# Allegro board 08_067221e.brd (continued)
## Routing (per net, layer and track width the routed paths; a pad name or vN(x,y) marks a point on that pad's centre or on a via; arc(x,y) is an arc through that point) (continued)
UNNAMED_8_ADAU145X_I261_CLKOUT: length 3.2
  TOP w0.178: R88.1 36.71,37.08 35.69,38.1 35.69,38.48 35.38,38.78 U6.23
UNNAMED_8_ADAU145X_I261_DVDD1: length 21.1
  TOP w0.254: C78.2 36.53,35.31 36.05,35.31 35.65,35.7 35.65,36.98 35.37,37.27 35.32,37.27 35.31,37.28 U6.20 ; U6.53 26.21,46.46 25.4,47.27 ; U6.71 24.41,37.28 24.13,37 24.13,36.23 C76.2 ; C73.2 36.45,45.47 36.03,45.05 35.82,45.05 35.55,44.78 U6.35
  TOP w0.508: v1(21.59,35.94) 21.59,35.68 C52.2 23.16,35.43 C76.2 ; C73.2 36.87,45.8 36.87,46.52 C36.2 v1(37.22,47.49) ; v1(38.23,35.31) C42.2 37.17,34.66 C78.2 ; 25.4,47.27 24.92,47.75 C69.2 23.61,47.92 C23.1 23.61,49.92 v1(23.37,50.16)
  vias: v1(22.35,50.16) v1(22.86,50.16)
UNNAMED_8_ADAU145X_I261_LRCLKIN2: length 1.9
  TOP w0.178: U6.66 23.58,39.78 R81.2
UNNAMED_8_ADAU145X_I261_LRCLKIN3: length 1.9
  TOP w0.203: v1(25.91,38.28) U6.69
  BOTTOM w0.178: R183.2 v1(25.91,38.28)
UNNAMED_8_ADAU145X_I261_LRCLKOUT0: length 5.4
  TOP w0.178: R44.1 36.22,48.55 35.62,48.55 35.2,48.13 34.84,48.13 34.08,47.37 33.75,47.37 33.21,46.83 U6.39
UNNAMED_8_ADAU145X_I261_LRCLKOUT1: length 16
  TOP w0.178: U6.42 31.71,47.22 33,48.51 33.6,48.51 33.81,48.72 33.81,51.92 v1(33.53,52.2) ; R75.1 v1(38.98,49.16)
  BOTTOM w0.178: v1(38.98,49.16) 37.85,50.29 37.85,51.69 37.34,52.2 v1(33.53,52.2)
UNNAMED_8_ADAU145X_I261_LRCLKOUT2: length 7.6
  TOP w0.178: R49.1 29.75,52.7 29.87,52.58 29.87,48.72 29.21,48.05 U6.47
UNNAMED_8_ADAU145X_I261_LRCLKOUT3: length 3.5
  TOP w0.178: R50.1 26.92,48.77 27.71,47.99 U6.50
UNNAMED_8_ADAU145X_I261_MISO: length 2
  TOP w0.178: R76.1 36.19,42.28 U6.30
UNNAMED_8_ADAU145X_I261_MP7: length 3.5
  TOP w0.178: U6.46 29.71,47.87 30.61,48.77 R69.2
UNNAMED_8_ADAU145X_I261_PLLFILT: length 4.3
  TOP w0.203: U6.16 33.21,35.53 33.61,35.13 33.61,34.2 C58.1
  TOP w0.508: C58.1 R99.1
UNNAMED_8_ADAU145X_I261_SCLK: length 2.3
  TOP w0.178: U6.31 35.54,42.78 36.7,43.94 R64.2
UNNAMED_8_ADAU145X_I261_SCLM: length 2.1
  TOP w0.178: U6.28 35.94,41.28 R79.1
UNNAMED_8_ADAU145X_I261_SDAM: length 1.9
  TOP w0.178: U6.29 36.58,41.78 R77.1
UNNAMED_8_ADAU145X_I261_SDATAIN0: length 1.9
  TOP w0.178: U6.59 23.46,43.28 R66.2
UNNAMED_8_ADAU145X_I261_SDATAIN1: length 1.8
  TOP w0.178: U6.62 24,41.78 23.88,41.91 R67.2
UNNAMED_8_ADAU145X_I261_SDATAIN2: length 1.9
  TOP w0.178: U6.67 23.53,39.28 R68.2
UNNAMED_8_ADAU145X_I261_SDATAIN3: length 2.2
  TOP w0.178: U6.70 24.32,37.78 24,37.46 24,37.46 R71.2
UNNAMED_8_ADAU145X_I261_SDATAOUT2: length 3.2
  TOP w0.178: U6.49 28.21,49.02 R84.1
UNNAMED_8_ADAU145X_I261_SDATAOUT3: length 4.6
  TOP w0.178: R52.1 24.64,48.73 24.98,48.39 25.91,48.39 26.71,47.59 U6.52
UNNAMED_8_ADAU145X_I261_SPDIFIN: length 4.7
  TOP w0.178: U6.4 27.21,35.59 26.54,34.92 26.54,33.66 26.29,33.4 25.92,33.4 R193.2
UNNAMED_8_ADAU145X_I261_SPDIFOUT: length 4.2
  TOP w0.178: U6.5 27.71,35.46 26.92,34.68 26.92,33.27 R116.1
UNNAMED_8_ADAU145X_I261_SSM: length 2.2
  TOP w0.178: R85.1 35.8,40.28 U6.26
UNNAMED_8_ADAU145X_I261_THDM: length 17.6
  TOP w0.178: U6.63 23.71,41.28 23.67,41.25 21.56,41.25 21.21,40.89 21.21,40.04 20.15,38.99 20.15,31.6 TP17.1
UNNAMED_8_ADAU145X_I261_THDP: length 18.8
  TOP w0.178: TP16.1 24.32,29.97 22.48,29.97 20.54,31.92 20.54,38.8 21.59,39.85 21.59,40.64 21.82,40.87 23.6,40.87 23.68,40.78 U6.64
UNNAMED_8_ADAU145X_I261_VDRIVE: length 11.5
  TOP w0.203: v1(26.71,38.09) U6.3
  BOTTOM w0.508: R175.1 22.86,44.69 Q3.1 23.5,42.92 26.71,39.72 v1(26.71,38.09)
UNNAMED_8_ADAU145X_I261_XTALIN: length 7.5
  TOP w0.178: U6.21 35.45,37.78 36.07,37.16 36.07,36.13 36.37,35.83 39,35.83 JP38.2
UNNAMED_8_CAP_I196_N2: length 1.4
  TOP w0.508: C86.2 35.56,31.41 R99.2
UNNAMED_8_CN3P_I266_N1: length 2.2
  TOP w0.203: JP38.1 R109.2
UNNAMED_8_CN3PV16_I292_VOUT: length 3.4
  TOP w0.203: P4.1 R103.1
UNNAMED_8_CN10P_I309_N1: length 4.4
  BOTTOM w0.203: P30.1 147.7,4.34 R234.2
UNNAMED_8_CN10P_I309_N3: length 4.4
  BOTTOM w0.203: R233.2 150.11,4.47 P30.3
UNNAMED_8_CN10P_I309_N4: length 5.9
  TOP w0.203: P30.4 153.19,7.57 153.19,10.89 R155.2
UNNAMED_8_CN10P_I309_N5: length 4.4
  BOTTOM w0.203: R232.2 152.65,4.47 P30.5
UNNAMED_8_CN10P_I309_N6: length 1.4
  BOTTOM w0.203: R225.2 P30.6
UNNAMED_8_CN10P_I309_N7: length 4.4
  BOTTOM w0.203: R235.2 155.19,4.47 P30.7
UNNAMED_8_CN10P_I309_N8: length 1.4
  BOTTOM w0.203: R223.2 P30.8
UNNAMED_8_CN10P_I309_N9: length 8.7
  TOP w0.203: JP42.2 P30.9
  BOTTOM w0.203: P30.9 159.03,3.25 R231.2
UNNAMED_8_DIOLED_I175_P: length 1.8
  TOP w0.178: DS4.A 38.1,51.46 R75.2
UNNAMED_8_DIOLED_I315_P: length 1.8
  TOP w0.203: R155.1 DS5.A
UNNAMED_8_RES_I3_N2: length 4
  TOP w0.203: R115.1 41.51,25.65 41.72,25.86 Y1.1 43.24,27.38 R110.2
UNNAMED_8_RES_I27_N1: length 1.9
  TOP w0.203: Y1.3 39.82,30.9 R109.1
UNNAMED_8_RES_I113_N2:
  vias: v1(22.35,52.45) v1(22.86,52.45) v1(23.37,52.45)
UNNAMED_9_AD1937_I165_ABCLK: length 8.6
  TOP w0.178: U7.28 53.57,43.98 v1(53.61,43.94) ; U7.21 57.08,46.44 56.9,46.62 56.9,46.66 R58.2
  TOP w0.203: U7.21 v1(57.08,43.99)
  BOTTOM w0.178: v1(53.61,43.94) 54.13,43.42 56.5,43.42 v1(57.08,43.99)
UNNAMED_9_AD1937_I165_ADC2LN: length 5
  TOP w0.254: R43.1 54.8,29.87 54.8,30.53 56.02,31.75 56.02,32.72 56.08,32.78 U7.58
UNNAMED_9_AD1937_I165_ADC2LP: length 5.2
  TOP w0.254: U7.57 55.56,33.99 55.56,31.94 53.82,30.2 53.82,29.98 R60.1
UNNAMED_9_AD1937_I165_ADC2RN: length 4.5
  TOP w0.254: U7.60 57.08,32.49 56.93,32.34 56.93,31.37 56.71,31.14 R61.1
UNNAMED_9_AD1937_I165_ADC2RP: length 4.7
  TOP w0.254: R124.1 55.63,30.71 56.48,31.56 56.48,32.53 56.57,32.63 U7.59
UNNAMED_9_AD1937_I165_ALRCLK: length 9.2
  TOP w0.178: U7.29 53.08,47 R59.2
  TOP w0.203: U7.22 56.57,44.25 56.54,44.22 56.54,43.77 56.57,43.74 56.57,43.62 56.1,43.14 53.38,43.14 53.08,43.45 U7.29
UNNAMED_9_AD1937_I165_ASDATA1: length 1.7
  TOP w0.203: U7.27 54.08,47.03 R105.1
UNNAMED_9_AD1937_I165_DSDATA1: length 1.7
  TOP w0.203: U7.20 R104.2
UNNAMED_9_AD1937_I165_FILTR: length 1.8
  TOP w0.254: U7.47 C127.2
UNNAMED_9_AD1937_I165_LF: length 2.1
  TOP w0.254: C60.2 57.57,31.9 U7.61
UNNAMED_9_AD1937_I165_SCL: length 5.7
  TOP w0.203: R132.1 49.52,46.3 50.8,45.02 50.8,43.19 50.53,42.93 U7.34
UNNAMED_9_AD1937_I165_SDA: length 13.5
  TOP w0.203: U7.31 52.08,43.87 53.21,42.74 58.48,42.74 60.83,45.09 R138.1
UNNAMED_10_ADG774_I1_D1: length 2.1
  TOP w0.178: U8.4 3.66,36.33 R92.2
UNNAMED_10_ADG774_I1_D2: length 2.4
  TOP w0.178: R111.2 3.46,31.62 4.36,32.52 U8.7
UNNAMED_10_ADG774_I1_D3: length 2
  TOP w0.178: R113.2 12.06,31.25 U8.9
UNNAMED_10_ADG774_I1_D4: length 1.9
  TOP w0.178: R100.2 12.44,35.06 U8.12
UNNAMED_10_ADG774_I1_ENN: length 3.1
  TOP w0.178: R83.1 R82.1 12.44,38.87 U8.15
UNNAMED_10_ADG774_I1_IN: length 15.7
  TOP w0.508: JP47.2 3.75,50.8 4.95,49.59 4.95,42.8 5.41,42.34 R80.1 U8.1
UNNAMED_10_ADG774_I1_S1A: length 2.4
  TOP w0.178: U8.2 4.43,38.87 R86.2
UNNAMED_10_ADG774_I1_S1B: length 2.3
  TOP w0.178: R90.1 4.04,37.6 U8.3
UNNAMED_10_ADG774_I1_S2A: length 2.1
  TOP w0.178: U8.5 3.56,35.06 R97.2
UNNAMED_10_ADG774_I1_S2B: length 2.2
  TOP w0.178: R102.1 3.94,33.79 U8.6
UNNAMED_10_ADG774_I1_S3A: length 1.9
  TOP w0.178: R106.2 12.44,33.79 U8.11
UNNAMED_10_ADG774_I1_S3B: length 2
  TOP w0.178: R108.1 12.19,32.52 U8.10
UNNAMED_10_ADG774_I1_S4A: length 2
  TOP w0.178: R89.2 12.06,37.6 U8.14
UNNAMED_10_ADG774_I1_VDD: length 9.5
  TOP w0.305: C38.2 11.05,41.66 11.68,41.02 13.21,41.02 13.45,40.77 R83.2
  TOP w0.508: 10.5,43.41 10.53,43.38 C38.2 10.53,40.21 U8.16 ; 10.5,43.41 E9.1 ; 10.5,43.41 C37.2
UNNAMED_10_ADMAX16823_I78_CS1: length 12.7
  TOP w0.203: R153.2 TP20.1 9.52,10.61 DS6.3 10.72,12.88 11.49,13.65 11.49,15.16 12.21,15.87 U10.15
UNNAMED_10_ADMAX16823_I78_CS2: length 11.5
  TOP w0.203: U10.14 11.56,15.8 11.05,15.29 11.05,14.22 10.76,13.94 DS6.2 TP22.1 R152.2
UNNAMED_10_ADMAX16823_I78_CS3: length 12.3
  TOP w0.203: U10.13 10.91,17.67 11.1,17.48 11.1,15.99 10.11,15 DS6.1 7.65,15 7.58,15.07 4.94,15.07 TP23.1 R151.2
UNNAMED_10_ADMAX16823_I78_LGC: length 1.6
  TOP w0.203: C15.2 8.96,18.22 U10.10
UNNAMED_10_ADMAX16823_I78_OUT1: length 16.4
  TOP w0.203: DS6.4 13.45,12.88 14.43,13.86 14.43,15.65 13.91,16.18 13.91,25.34 13.26,25.98 12.41,25.98 12.21,25.78 U10.2
UNNAMED_10_ADMAX16823_I78_OUT2: length 12.6
  TOP w0.203: DS6.5 13.45,13.94 14.03,14.52 14.03,15.48 13.46,16.05 13.46,24.84 13.26,25.04 U10.1
UNNAMED_10_ADMAX16823_I78_OUT3: length 4.4
  TOP w0.203: DS6.6 12.92,18.4 12.86,18.47 U10.16
UNNAMED_10_ADMAX16823_I78_REG: length 1.5
  TOP w0.203: U10.11 9.61,17.94 C87.2
UNNAMED_10_FERRITE_I73_N1: length 1.7
  TOP w0.508: C85.2 7.18,19.95 ; C85.2 7.76,19.41 ; C85.2 6.59,19.41
UNNAMED_10_RES_I13_N2: length 11.5
  TOP w0.178: R108.2 v1(14.23,32.26)
  TOP w0.203: U10.5 v1(10.26,27.94)
  BOTTOM w0.178: v1(10.26,27.94) 12.19,27.94 14.22,29.97 14.22,32.25 v1(14.23,32.26) R108.2
UNNAMED_10_RES_I16_N2: length 17.2
  TOP w0.178: R102.2 v1(2.42,32.52) 2.43,32.51 3.81,32.51 4.21,32.91 4.21,32.96 4.39,33.15 6.6,33.15 6.93,32.82 7.95,32.82 8.25,32.51 8.25,29.97 9.53,28.7 10.73,28.7 10.91,28.52 U10.4
  BOTTOM w0.178: R102.2 v1(2.42,32.52)
UNNAMED_10_RES_I19_N2: length 22.9
  TOP w0.178: R90.2 v1(2.42,37.4) 3.69,37.4 4.1,36.99 6.45,36.99 7.17,37.72 8.38,37.72 8.65,37.45 8.65,30.12 9.68,29.08 11.05,29.08 11.29,28.84 11.29,28.84 11.56,28.57 U10.3
  BOTTOM w0.178: R90.2 v1(2.42,37.4)
UNNAMED_11_CAP_I16_N2: length 10.7
  TOP w0.508: 122.41,15.56 E12.1 ; E12.1 123.16,16.43 ; E12.1 123.16,14.68 ; C75.2 v1(120.92,19.08) ; C89.2 v1(110.92,13.55) ; C96.2 v1(109.71,3.08) ; C77.2 v1(101.34,19.08)
  BOTTOM w0.203: v1(110.92,14.63) v1(110.92,13.55)
  BOTTOM w0.508: v1(120.92,20.4) v1(120.92,19.08) ; v1(100.92,20.4) 101.34,19.99 v1(101.34,19.08) ; v1(110.92,3.08) v1(109.71,3.08)
  vias: v1(112.6,3.9) v1(122.05,16.26) v1(122.05,15.62) v1(122.05,14.99) v1(122.6,21.22)
UNNAMED_11_CN2P_I108_N1: length 2.3
  TOP w0.203: JP3.1 R74.1
UNNAMED_11_CN2P_I108_N2: length 10
  TOP w0.203: R246.2 U21.7 137.92,9.4 137.67,9.14 137.67,5.46 136.27,4.06
UNNAMED_11_FERRITE_I94_N1: length 2
  TOP w0.508: E16.1 139.85,10.69 U21.8
UNNAMED_11_IC24XX512_I83_A0: length 3.3
  TOP w0.203: 134.75,10.67 v1(133.1,10.67) R15.1
  BOTTOM w0.203: R16.2 v1(133.1,10.67)
UNNAMED_11_IC24XX512_I83_A1: length 3.3
  TOP w0.203: 134.75,9.4 v1(133.1,9.4) R19.1
  BOTTOM w0.203: R24.2 v1(133.1,9.4)
UNNAMED_11_IC24XX512_I83_A2: length 3.3
  TOP w0.203: 134.75,8.13 v1(133.1,8.13) R26.1
  BOTTOM w0.203: R30.2 v1(133.1,8.13)
UNNAMED_11_IC24XX512_I83_SCL: length 2
  TOP w0.203: 139.83,8.13 R25.1
UNNAMED_11_IC24XX512_I83_SDA: length 2
  TOP w0.203: U21.5 R29.1
UNNAMED_11_ICT3902_I102_CLK: length 44.8
  TOP w0.203: R157.1 v1(109.79,15.45)
  BOTTOM w0.203: 111.63,12.95 111.63,14.74 110.92,15.45 ; 111.63,12.95 112.9,12.95 113.92,13.97 113.92,15.62 115.57,17.27 117.73,17.27 119.13,18.67 119.13,19.81 120.54,21.22 v1(120.92,21.22) ; 111.63,12.95 109.6,10.92 109.6,5.22 v1(110.92,3.9) ; v1(110.92,15.45) v1(109.79,15.45) 107.21,18.03 100.2,18.03 99.57,18.67 99.57,20.83 99.96,21.22 v1(100.92,21.22) ; v1(110.92,15.45) 110.92,15.45 ; v1(110.92,15.45) 110.92,15.45 ; v1(110.92,15.45) 110.92,15.45 ; 110.92,15.45 110.92,15.45
UNNAMED_11_ICT3902_I102_DATA: length 2.1
  TOP w0.203: R130.1 v1(122.6,19.11)
  BOTTOM w0.203: v1(122.6,19.11) v1(122.6,20.4)
UNNAMED_11_ICT3902_I103_DATA: length 2.4
  TOP w0.203: R131.1 v1(103.37,19.11)
  BOTTOM w0.203: v1(102.6,20.4) 103.37,19.63 v1(103.37,19.11)
UNNAMED_11_ICT3902_I104_DATA: length 2
  TOP w0.203: R158.1 v1(113.83,3.08)
  BOTTOM w0.203: v1(112.6,3.08) v1(113.83,3.08)
UNNAMED_11_ICT3902_I105_DATA: length 1.9
  TOP w0.203: R141.1 v1(112.6,13.59)
  BOTTOM w0.203: v1(112.6,14.63) v1(112.6,13.59)
UNNAMED_12_ADLT3502_I229_BD: length 14.8
  L3_SIG w0.305: v1(58.86,61.02) 59.4,60.49 59.4,58.59 60.33,57.66 63.37,57.66 64.77,56.26 v1(64.77,52.58)
  BOTTOM w0.203: U16.2 59.01,61.94 R160.1 v1(58.86,61.02)
UNNAMED_12_ADLT3502_I229_BOOST: length 1.3
  BOTTOM w0.203: U16.7 C113.1
UNNAMED_12_ADLT3502_I229_DA: length 4.3
  BOTTOM w0.203: U16.6 62.65,62.39 62.87,62.61 62.87,63.25 62.36,63.75 62.36,65.02 D1.A
UNNAMED_12_ADLT3502_I229_SHDNN: length 5.9
  BOTTOM w0.203: R162.1 55.53,62.79 C105.2 56.71,63.23 56.91,63.44 60,63.44 60.2,63.23 U16.4
UNNAMED_12_ADLT3502_I229_SW: length 4.5
  BOTTOM w0.203: 61.98,61.28 61.98,61.28 U16.8
  BOTTOM w0.508: C113.2 63.89,60.94 ; C113.2 62.72,60.94 ; C113.2 63.31,60.39 ; D1.C 65.5,65.53 ; D1.C 64.65,64.68 ; D1.C 64.65,66.38
UNNAMED_12_ADLTC4368V2_I398_SHDNN: length 2.3
  TOP w0.254: R27.1 54.47,56.98 U3.6
UNNAMED_12_ADP2360_I325_FB: length 4.6
  BOTTOM w0.203: U19.4 85.33,60.22 85.85,59.69 R164.2 R167.1 85.92,57.36 C115.2
UNNAMED_12_ADP2360_I325_ITH: length 1.8
  BOTTOM w0.203: R163.2 85.83,60.87 U19.3
UNNAMED_12_ADP2360_I325_SS: length 1.4
  BOTTOM w0.203: U19.5 C25.2
UNNAMED_12_CAP_I278_N2: length 19
  TOP w0.508: 28.51,59.31 TP1.1 ; TP1.1 30.29,57.53 ; TP1.1 30.29,59.31 ; TP1.1 28.51,57.53 ; 23.89,62.8 P1.1 ; P1.1 23.89,60.49 ; P1.1 26.2,62.8 ; P1.1 26.2,60.49 ; 32.63,62.78 P2.1 ; P2.1 35.25,62.78 ; P2.1 35.25,65.4 ; P2.1 32.63,65.4
UNNAMED_12_CAP_I279_N2: length 2.8
  TOP w0.254: U3.1 48.71,58.98 48.46,59.23 48.46,59.56 v1(48.45,59.56)
  TOP w0.508: R17.2 v1(45.02,60.07) ; R10.2 v1(43.43,61.32)
  vias: v1(39.69,59.82) v1(39.69,59.12) v1(40.45,59.82) v1(40.45,59.12) v1(41.21,59.82) v1(41.21,59.12) v1(46.48,64.33) v1(46.48,63.56) v1(46.48,62.86) v1(46.48,62.1) v1(49.21,59.56)
UNNAMED_12_CAP_I301_N2: length 13.2
  L3_SIG w0.305: v1(80.58,52.01) 85.72,57.15 v1(88.71,57.15)
  BOTTOM w0.305: v1(88.71,57.15) C115.1 87.76,57.18 87.76,58.1 87.31,58.55 R167.2
UNNAMED_12_CAP_I303_N2: length 3.6
  TOP w0.254: U3.4 47.44,57.48 46.94,56.97 R28.1 C6.2
UNNAMED_12_CAP_I350_N2: length 1.1
  TOP w0.203: R13.1 C3.2
UNNAMED_12_DIOLED_I290_P: length 1.6
  TOP w0.508: DS8.A R33.1
UNNAMED_12_DIOLED_I334_P: length 1.9
  TOP w0.508: DS2.A R10.1
UNNAMED_12_DIOLED_I356_P: length 1.6
  TOP w0.508: R36.1 DS7.A
UNNAMED_12_RES_I210_N1: length 3.4
  TOP w0.254: U3.3 46.81,57.98 R20.1 R23.2
UNNAMED_12_RES_I210_N2: length 3.6
  TOP w0.254: U3.2 47.46,58.48 46.95,58.98 R20.2 R17.1
UNNAMED_12_TRANNMOSFETDUAL_I282_S:
  vias: v1(54.93,65.53) v1(54.93,64.14) v1(55.69,65.53) v1(55.69,64.14)
UNNAMED_13_ADA48412_I26_: length 4.2
  BOTTOM w0.203: R205.2 C157.1 R204.1 22.17,14.78 U18.6
UNNAMED_13_ADA48412_I26_OUT: length 12.6
  BOTTOM w0.203: R214.2 26.09,15.72 25.76,16.05 ; 25.76,16.05 U18.7 22.17,16.05 R204.2 C157.2 ; 25.76,16.05 26.25,16.53 R200.1
UNNAMED_13_ADA48412_I42_: length 7.9
  BOTTOM w0.203: R214.1 27.09,15.28 27.86,16.05 U18.2 31.02,16.05 R201.1
UNNAMED_13_ADA48412_I42_OUT: length 5.5
  BOTTOM w0.203: R198.1 27.6,17.46 27.74,17.32 U18.1 31.06,17.32 R201.2
UNNAMED_13_ADA48412_I53_: length 6.7
  BOTTOM w0.203: R213.1 38.47,14.11 37.8,14.78 U17.6 34.68,14.78 R202.1
UNNAMED_13_ADA48412_I53_OUT: length 6.9
  BOTTOM w0.203: R202.2 34.42,16.05 U17.7 37.89,16.05 38.44,16.6 R197.1
UNNAMED_13_ADA48412_I115_: length 3.3
  BOTTOM w0.203: R221.2 C161.2 57.66,22.67 57.15,23.18 U5.3
UNNAMED_13_ADA48412_I115__1: length 5.2
  BOTTOM w0.203: R219.2 C155.1 57.29,24.72 57.02,24.45 U5.2
UNNAMED_13_ADA48412_I115_OUT: length 9.3
  TOP w0.203: v1(54.29,25.78) 53.09,25.78 51.05,23.74 R236.1
  BOTTOM w0.203: R217.2 C155.2 U5.1 56.2,25.78 v1(54.29,25.78)
UNNAMED_13_ADA48412_I139_: length 3.2
  BOTTOM w0.203: R224.2 C165.2 U5.5
UNNAMED_13_ADA48412_I139__1: length 3.4
  BOTTOM w0.203: R222.2 48.14,23.45 C164.1 50.02,23.45 50.29,23.18 U5.6
UNNAMED_13_ADA48412_I139_OUT: length 12
  TOP w0.203: R237.1 45.34,23.56 47.18,25.4 v1(48.05,25.4)
  BOTTOM w0.203: U5.7 C164.2 R218.2 48.01,24.46 48.01,25.34 48.05,25.38 v1(48.05,25.4)
UNNAMED_13_ADA48412_I160_: length 4.8
  BOTTOM w0.203: U17.2 R208.1 C158.1 R207.2
UNNAMED_13_ADA48412_I160_OUT: length 13
  BOTTOM w0.203: R196.1 39.85,17.55 40.09,17.32 ; 40.09,17.32 40.09,17.29 39.47,16.68 R213.2 ; 40.09,17.32 U17.1 42.78,17.32 43.05,17.05 R208.2 C158.2
UNNAMED_13_CAP_I35_N2: length 13.8
  TOP w0.203: C91.1 27.11,13.47 26.54,14.03 C93.2 R145.2 P29.3 22.19,9.5 TP5.1
UNNAMED_13_CAP_I36_N2: length 11
  TOP w0.203: C91.2 28.13,17.26 28.13,22.48 27.88,22.73 S1.2 24.83,22.73 24.31,22.21 R129.1
UNNAMED_13_CAP_I69_N1: length 24.9
  TOP w0.203: TP6.1 21.18,7.94 34.04,7.94 34.31,8.21 P29.2 R144.2 C92.2 32,14.03 31.44,13.47 C90.1
UNNAMED_13_CAP_I69_N2: length 10.2
  TOP w0.203: R123.1 33.9,23.23 33.4,22.73 S1.5 30.69,22.73 30.42,22.46 30.42,17.27 C90.2
UNNAMED_13_CAP_I87_N1: length 2.7
  BOTTOM w0.203: R197.2 37.47,19.96 C143.1
UNNAMED_13_CAP_I88_N1: length 2.7
  BOTTOM w0.203: C142.1 40.83,19.96 R196.2
UNNAMED_13_CAP_I89_N1: length 2.7
  BOTTOM w0.203: C147.1 25.27,19.96 R200.2
UNNAMED_13_CAP_I90_N1: length 2.7
  BOTTOM w0.203: C144.1 28.57,19.96 R198.2
UNNAMED_13_CAP_I126_N2: length 3.1
  BOTTOM w0.203: R217.1 R219.1 C106.2 R194.2
UNNAMED_13_CAP_I128_N1: length 3.1
  BOTTOM w0.203: R221.1 C166.2 C148.1 R192.2
UNNAMED_13_CAP_I144_N2: length 3.2
  BOTTOM w0.203: R222.1 R218.1 C149.2 46.99,25.46 R212.2
UNNAMED_13_CAP_I147_N1: length 3.1
  BOTTOM w0.203: C167.2 C150.1 47,20.83 R224.1 R211.2
UNNAMED_13_CAP_I164_N1: length 1.1
  BOTTOM w0.203: C167.1 R216.2
UNNAMED_13_CAP_I165_N1: length 1
  BOTTOM w0.203: C166.1 R215.2
UNNAMED_13_CAPP_I155_N1: length 2.9
  TOP w0.203: R236.2 49.15,23.56 48.3,22.71 C19.P
UNNAMED_13_CAPP_I155_N2: length 7.2
  TOP w0.203: P28.2 R128.2 C19.N
UNNAMED_13_CAPP_I158_N1: length 2.9
  TOP w0.203: R237.2 39.12,23.56 38.3,22.75 C130.P
UNNAMED_13_CAPP_I158_N2: length 7.2
  TOP w0.203: C130.N R250.2 P28.3
UNNAMED_13_RES_I31_N2: length 9.8
  TOP w0.203: S1.3 R129.2 v1(23.48,20.24)
  BOTTOM w0.203: v1(23.48,20.24) 21.83,20.24 19.88,18.29 19.88,15.91 R205.1
UNNAMED_13_RES_I67_N1: length 23.8
  TOP w0.203: v1(42.55,24.23) 37.19,24.23 35.19,22.23 R123.2 34.42,20.57 34.09,20.24 S1.6
  BOTTOM w0.203: R207.1 46.29,17.7 46.09,17.91 42.88,17.91 42.55,18.24 v1(42.55,24.23)
UNNAMED_14_7404V6_I71_Y: length 2.3
  TOP w0.203: R239.1 143.39,16.9 143.27,17.03 143.27,17.77 143.12,17.91 U28.4
UNNAMED_14_ADMAX22503E_I16_A: length 21.6
  TOP w0.203: T2.8 66.01,21.12 66.55,21.65 66.84,21.65 R188.2 v1(68.17,23.94)
  BOTTOM w0.203: v1(68.17,23.94) 68.17,23.01 68.71,22.48 70.23,22.48 71.44,21.27 71.44,15.76 70.71,15.03 D8.6 69.14,14.51 67.03,14.51 66.37,15.17 U20.12
UNNAMED_14_ADMAX22503E_I16_B: length 22.3
  TOP w0.203: T2.5 72.03,21.12 71.5,21.65 71.21,21.65 R188.1 v1(69.87,23.98)
  BOTTOM w0.203: U20.11 67.65,16.44 D8.3 68.7,16.33 69.58,17.21 70.79,17.21 70.99,17.41 70.99,20.83 70.1,21.72 68.83,21.72 67.44,23.11 67.44,24.32 67.64,24.52 68.44,24.52 68.99,23.98 v1(69.87,23.98)
UNNAMED_14_ADMAX22503E_I16_Y: length 33.7
  TOP w0.203: v1(53.34,23.24) 53.59,23.49 55.37,23.49 56.64,24.77 58.04,24.77 58.29,24.51 58.29,23.76 R206.1
  BOTTOM w0.203: v1(53.34,23.24) 53.34,22.38 53.49,22.23 53.49,18 59.49,12 61.85,12 64.05,14.2 64.05,17.94 65.08,18.98 U20.9 66.35,18.98 66.57,19.2 D9.6
UNNAMED_14_ADMAX22503E_I16_Z: length 32.8
  TOP w0.203: v1(52.96,22.01) 53.56,22.61 R209.1 T3.8
  BOTTOM w0.203: D9.3 69.09,17.34 66.87,17.34 66.74,17.46 65.96,17.46 U20.10 64.66,17.71 64.45,17.51 64.45,13.91 62.1,11.56 59.25,11.56 52.96,17.84 v1(52.96,22.01)
UNNAMED_14_CAP_I5_N1: length 2.2
  TOP w0.203: C160.1 T3.5
UNNAMED_14_CAP_I5_N2: length 1.5
  TOP w0.203: C160.2 R210.1
UNNAMED_14_CAP_I27_N2: length 35.8
  TOP w0.508: C153.2 77.22,3.56
  TOP w1.016: P3.4 67.94,6.46 ; P3.4 65.99,8.41 ; P3.4 65.99,4.52 ; 69.05,1.96 P3.3 ; P3.3 70.99,3.91 ; P3.3 72.94,1.96 ; 74.05,6.46 P3.2 ; P3.2 75.99,4.52 ; P3.2 75.99,8.41
  BOTTOM w1.016: P3.4 67.94,6.46 ; P3.4 65.99,4.52 ; P3.4 65.99,8.41 ; 75.99,4.52 P3.2 ; P3.2 74.05,6.46 ; P3.2 75.99,8.41 ; 69.05,1.96 P3.3 ; P3.3 72.94,1.96 ; P3.3 70.99,3.91
UNNAMED_14_CN2P_I102_N1: length 2.2
  TOP w0.178: JP2.1 R180.1
UNNAMED_14_CN4PV4_I1_N1: length 6.3
  TOP w0.762: P5.1 58.62,8.13 60.16,8.13 60.79,8.76 T3.4
UNNAMED_14_CN4PV4_I1_N2: length 35.9
  TOP w0.508: C168.2 50.74,3.62
  TOP w1.016: 51.96,4.52 P5.4 ; P5.4 53.9,6.46 ; P5.4 51.96,8.41 ; P5.3 58.9,1.96 ; P5.3 56.96,3.91 ; P5.3 55.02,1.96 ; 60.02,6.46 P5.2 ; P5.2 61.96,4.52 ; P5.2 61.96,8.41
  BOTTOM w1.016: P5.4 53.9,6.46 ; P5.4 51.96,4.52 ; P5.4 51.96,8.41 ; P5.3 58.9,1.96 ; P5.3 55.02,1.96 ; P5.3 56.96,3.91 ; P5.2 61.96,8.41 ; P5.2 61.96,4.52 ; P5.2 60.02,6.46
UNNAMED_14_CN4PV4_I26_N1: length 4.2
  TOP w0.762: P3.1 72.03,7.5 T2.4
UNNAMED_14_DIOLED_I76_P: length 3.2
  TOP w0.203: DS11.A 143.81,19.94 144.02,19.74 R239.2
UNNAMED_14_RES_I37_N2: length 2.7
  TOP w0.203: R209.2 R210.2 R206.2
USB_RESET: length 148.9
  TOP w0.203: U1.2 C2.2 R5.2 111.56,64.58 v1(110.74,64.58)
  L3_SIG w0.178: v1(153.91,12.06) 154.56,12.72 154.56,19.3 152.91,20.95 148.59,20.95 146.05,23.49 127.98,23.49 126.71,24.77 120.14,24.77 116.96,27.94 113.85,27.94 112.37,29.42 109.37,29.42 106.41,32.38 104.39,32.38 94.48,42.3 85.59,42.3 79.24,48.65 79.24,60.38 82.35,63.5 84.96,63.5 86.09,62.37 88.13,62.37 89.03,61.47 99.19,61.47 102.3,64.58 v1(110.74,64.58)
  BOTTOM w0.203: R225.1 v1(153.91,12.06)
USBI_SCL: length 182.7
  TOP w0.178: R64.1 v1(38.44,43.94)
  TOP w0.203: U27.4 131.71,18.69 R70.1 v1(132.59,18.8)
  L3_SIG w0.178: v1(10.67,46.67) 11.72,47.73 18.95,47.73 19.99,46.69 19.99,39.95 20.69,39.26 20.69,36.11 21.76,35.04 35.55,35.04 35.79,35.28 35.79,42.68 36.67,43.56 38.05,43.56 v1(38.44,43.94) 38.8,43.58 39.05,43.58 39.64,44.17 41.81,44.17 42.55,43.43 42.55,41.91 43.29,41.16 94,41.16 102.8,32.36 102.8,29.47 103.99,28.28 111.89,28.28 113.38,26.8 116.49,26.8 119.66,23.62 126.24,23.62 131.06,18.8 v1(132.59,18.8)
  BOTTOM w0.203: R234.1 148.59,9.02 148.59,10.29 146.69,12.19 141.61,12.19 135.28,18.52 135.28,19.02 134.86,19.43 133.22,19.43 v1(132.59,18.8) ; P32.87 v1(10.67,46.67)
USBI_SDA: length 184
  TOP w0.178: R76.2 v1(38.44,42.8)
  TOP w0.203: v1(137.29,18.8) R55.1 136.54,18.77 U26.4
  L3_SIG w0.178: v1(137.29,18.8) 136.78,18.29 134.97,18.29 134.96,18.28 119.99,18.28 119.38,18.88 119.38,23.37 116.33,26.42 113.22,26.42 111.74,27.9 103.83,27.9 102.42,29.31 102.42,32.2 99.44,35.18 98.43,35.18 92.82,40.78 43.04,40.78 42.16,41.66 42.16,43.18 41.55,43.79 39.8,43.79 39.19,43.18 38.82,43.18 v1(38.44,42.8) 38.05,43.18 36.83,43.18 36.17,42.52 36.17,35.12 35.71,34.66 21.6,34.66 20.31,35.95 20.31,39.1 19.56,39.85 19.56,44.58 19.18,44.96 11.11,44.96 v1(10.67,45.4)
  BOTTOM w0.203: v1(137.29,18.8) 137.29,17.14 141.73,12.7 146.94,12.7 149.1,10.54 149.1,9.15 R233.1 ; P32.83 v1(10.67,45.4)
VOUT2_3V3: length 12.6
  TOP w0.254: U9.45 108.69,39.17 108.97,39.44 v1(108.97,39.75) ; U9.31 118.62,35.42 C57.2
  TOP w0.508: C59.2 121.79,35.44 v1(121.79,36.83) ; v1(108.97,40.26) v1(108.97,39.75)
  L4_PWR w0.508: TP15.1 122.68,39.24 ; TP15.1 120.91,37.47 ; TP15.1 122.68,37.47
  BOTTOM w0.508: v1(108.97,39.75) v1(108.97,40.26)
  vias: v1(121.16,36.83) v1(121.16,34.04) v1(121.79,34.04) v1(122.43,36.83) v1(122.43,34.04)
WKUP_24V: length 10.4
  TOP w0.381: JP4.1 142.24,35.56 143,34.8 Q2.4
  L4_PWR w0.508: JP4.1 139.83,36.74 ; JP4.1 139.83,34.38 ; JP4.1 138.65,35.56
  vias: v1(41.72,56.26) v1(41.72,55.5) v1(41.72,54.74) v1(42.55,56.26) v1(42.55,55.5) v1(42.55,54.74)
YLED_ANODE: length 2.1
  BOTTOM w0.508: R46.1 166.14,17.18 P22.9
YLED_CATHODE: length 27.3
  TOP w0.508: Q2.1 v1(154,34.8)
  BOTTOM w0.508: v1(154,34.8) 154.56,34.8 156.08,36.32 158.67,36.32 166.88,28.11 166.88,23.62 168.2,22.3 P22.10

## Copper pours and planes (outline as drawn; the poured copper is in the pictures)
DGND on TOP: 1.27,69.21 176.53,69.21 176.53,50.65 175.51,50.65 175.51,42.68 176.53,42.68 176.53,37.59 175.13,37.59 175.13,35.18 175.03,35.18 175.03,33.53 176.53,33.53 176.53,28.17 175.51,28.17 175.51,20.2 176.53,20.2 176.53,9.91 162.28,9.91 162.28,9.05 162.28,9.05 176.53,9.05 176.53,1.27 1.27,1.27 ; 46 cut-outs
DGND on TOP: 174.31,55.63 176.53,55.63 176.53,50.65 175.52,50.65 175.52,42.68 176.53,42.68 176.53,37.66 174.31,37.66
DGND on BOTTOM: 1.27,69.21 176.53,69.21 176.53,50.65 175.51,50.65 175.51,42.68 176.53,42.68 176.53,34.96 149.63,34.96 149.63,33.53 176.53,33.53 176.53,28.17 176.15,28.17 176.15,20.2 176.53,20.2 176.53,15.37 162.31,15.37 162.31,9.91 174.88,9.91 174.88,9.14 162.31,9.14 162.31,9.04 176.53,9.04 176.53,1.27 1.27,1.27 ; 45 cut-outs
DGND on L2_GND: 1.27,69.21 176.53,69.21 176.53,50.65 175.51,50.65 175.51,42.68 176.53,42.68 176.53,34.57 175.4,34.57 175.4,33.4 176.53,33.4 176.53,28.17 176.02,28.17 176.02,31.24 174.75,31.24 174.75,16.89 176.02,16.89 176.02,20.2 176.53,20.2 176.53,14.99 175.03,14.99 175.03,9.04 176.53,9.04 176.53,1.27 1.27,1.27
DGND on L3_SIG: 1.27,69.21 176.53,69.21 176.53,50.65 175.51,50.65 175.51,42.68 176.53,42.68 176.53,34.57 175.4,34.57 175.4,33.02 176.53,33.02 176.53,28.17 175.51,28.17 175.51,20.2 176.53,20.2 176.53,15.49 175.03,15.49 175.03,9.04 176.53,9.04 176.53,1.27 1.27,1.27 ; 63 cut-outs
DGND on L4_PWR: 107.95,33.78 108.08,33.78 108.08,33.15 112.14,33.15 112.14,37.21 107.95,37.21
DGND on L5_GND: 1.27,69.21 176.53,69.21 176.53,50.65 175.51,50.65 175.51,42.68 176.53,42.68 176.53,34.57 175.37,34.57 175.37,33.4 176.53,33.4 176.53,28.17 175.77,28.17 175.77,31.37 174.5,31.37 174.5,16.89 175.77,16.89 175.77,20.2 176.53,20.2 176.53,14.99 175.03,14.99 175.03,9.04 176.53,9.04 176.53,1.27 1.27,1.27
GND_ISO on TOP: 150.22,36.96 150.22,33.02 156.97,33.02 156.97,28.87 160.4,28.87 160.4,28.19 163.83,28.19 163.83,27.12 165.1,27.12 165.1,23.37 163.83,23.37 163.83,10.29 173.48,10.29 173.48,14.99 173.86,15.37 173.86,33.02 165.35,33.02 165.35,36.96
GND_ISO on BOTTOM: 150.22,36.96 150.22,33.02 156.97,33.02 156.97,28.87 160.53,28.87 163.55,28.83 163.55,28.31 164.22,28.31 165.1,27.43 165.1,23.37 163.83,23.37 163.83,10.29 173.48,10.29 173.48,14.99 173.86,15.37 173.86,33.02 165.35,33.02 165.35,36.96 ; 1 cut-out
GND_ISO on L2_GND: 150.22,36.96 150.22,33.02 156.97,33.02 156.97,28.87 159.77,28.87 159.77,28.19 163.83,28.19 163.83,27.13 164.75,27.13 165.1,26.78 165.1,23.37 164.59,23.37 164.59,23.37 163.83,23.37 163.83,10.29 173.48,10.29 173.48,14.99 173.86,15.37 173.86,33.02 165.35,33.02 165.35,36.96
GND_ISO on L3_SIG: 150.22,36.96 150.22,33.02 156.97,33.02 156.97,28.87 162.31,28.87 162.31,28.32 164.21,28.32 165.1,27.43 165.1,23.37 163.83,23.37 163.83,10.29 173.48,10.29 173.48,14.99 173.86,15.37 173.86,33.02 165.35,33.02 165.35,36.96
GND_ISO on L4_PWR: 150.22,36.96 150.22,33.02 156.97,33.02 156.97,28.87 160.7,28.87 160.66,28.83 163.55,28.83 163.55,28.32 163.56,28.32 164.21,28.32 165.1,27.43 165.1,23.37 163.83,23.37 163.83,10.29 173.48,10.29 173.48,14.99 173.86,15.37 173.86,33.02 165.35,33.02 165.35,36.96
GND_ISO on L5_GND: 150.22,36.96 150.22,33.02 156.97,33.02 156.97,28.87 163.55,28.87 163.55,28.32 164.22,28.32 165.1,27.43 165.1,23.37 163.83,23.37 163.83,10.29 173.48,10.29 173.48,14.99 173.86,15.37 173.86,33.02 165.35,33.02 165.35,36.96
VDD_3V3 on BOTTOM (solid shape): 59.44,51.69 58.55,51.69 57.86,52.37 55.68,52.37 55.24,51.94 54.04,51.94 53.91,52.07 53.91,54.1 54.29,54.48 59.44,54.48
VDD_3V3 on TOP: 124.33,16.76 124.33,14.35 125.98,14.35 126.24,14.61 126.24,16.51 125.98,16.76
VDD_3V3 on TOP: 60.77,25.84 60.52,26.1 60.52,27.94 60.77,28.19 61.53,28.19 61.94,28.61 61.94,30.13 62.17,30.35 63.31,30.35 63.5,30.16 63.5,26.42 62.93,25.84
VDD_3V3 on TOP: 58.77,51.15 59.18,51.56 61.72,51.56 61.91,51.37 61.91,50.36 61.72,50.16 60.26,50.16 60.13,50.04 60.13,48.2 59.5,47.56 59.5,46.93 59.25,46.67 59.25,44.58 59.18,44.51 58.93,44.51 58.93,46.61 58.77,46.77
VDD_3V3 on TOP: 19.56,58.55 19.56,56.52 20.83,56.52 20.83,58.55
VDD_3V3 on TOP: 35.36,28.83 36.7,28.83 36.96,29.08 36.96,30.28 36.86,30.38 36.55,30.38 36.45,30.28 36.45,29.97 36.32,29.84 35.36,29.84
VDD_3V3 on BOTTOM: 64.71,14.29 64.71,12.26 70.74,12.26 70.74,14.29
VDD_3V3 on BOTTOM: 21.59,47.88 25.02,47.88 25.02,49.53 21.59,49.53 21.46,49.4 21.46,48.01
VDD_3V3 on BOTTOM: 129.03,38.48 129.03,39.24 128.91,39.37 126.95,39.37 126.95,38.35 128.91,38.35
VDD_3V3 on L4_PWR: 99.31,69.09 176.4,69.09 176.4,53.71 166.56,53.71 166.56,52.7 163.58,52.7 163.58,49.28 166.37,49.28 166.37,37.72 151.13,37.72 151.13,32.89 167.13,32.89 167.13,13.46 176.4,13.46 176.4,11.05 175.03,11.05 175.03,9.04 176.4,9.04 176.4,1.4 49.53,1.4 49.53,17.02 59.82,17.02 59.82,28.7 52.77,28.7 52.77,27.24 47.05,27.24 47.05,21.27 36.39,21.27 36.39,16.89 21.84,16.89 21.84,27.56 6.16,27.56 6.16,59.94 31.18,59.94 31.18,62.17 90.23,62.17 90.23,58.8 95.25,58.8 95.25,54.04 99.31,54.04 ; 5 cut-outs
VDD_5V on BOTTOM (solid shape): 90.8,53.28 91.38,52.7 93.6,52.7 94.36,51.94 94.36,50.42 93.31,49.37 87.79,49.37 87.5,49.66 87.5,54.36 88.52,54.36 88.71,54.55 90.8,54.55
VDD_5V on L3_SIG: 159.89,47.12 157.23,47.12 157.23,48.39 89.22,48.39 89.22,52.39 159.89,52.39
VDD_5V_BPORT on BOTTOM (solid shape): 85.92,54.29 85.92,51.31 85.85,51.24 83.12,51.24 82.99,51.37 82.99,54.55 85.66,54.55
VDD_5V_BPORT on L3_SIG: 84.84,53.85 84.84,51.94 86.87,51.94 86.87,52.83 113.03,52.83 113.03,56.01 91.44,56.01 90.3,54.86 85.85,54.86
(no net) on TOP: 48.96,64.58 46.04,64.58 45.91,64.45 45.91,61.98 46.1,61.79 48.83,61.79 48.96,61.91
(no net) on TOP: 25.65,59.21 25.83,59.03 25.83,55.75 25.96,55.63 32.44,55.63 33.45,54.61 34.44,54.61 34.44,59.91 35.94,61.4 35.94,65.28 35.56,65.66 30.23,65.66 29.59,65.02 24.51,65.02 23.24,63.75 23.24,60.58 24.61,59.21
(no net) on TOP: 53.4,58.8 50.86,58.8 50.55,59.12 50.55,66.8 50.86,67.12 54.04,67.12 54.17,66.99 54.17,66.55 54.1,66.48 52.07,66.48 51.94,66.36 51.94,64.71 52.07,64.58 54.17,64.58 54.17,63.94 52.01,63.94 51.94,63.88 51.94,61.79 52.32,61.4 53.28,61.4 53.4,61.28
(no net) on TOP: 35.81,54.61 36.78,54.61 37.37,55.2 37.37,56.93 37.72,57.28 41.66,57.28 41.66,59.82 41.27,60.2 36.32,60.2 35.81,59.69
(no net) on TOP: 52.13,58.1 53.53,58.1 54.17,58.74 56.96,58.74 57.79,59.56 97.54,59.56 97.92,59.18 97.92,57.02 94.74,53.85 89.03,53.85 88.26,54.61 81.66,54.61 79.12,52.07 68.45,52.07 67.18,50.8 67.18,49.02 66.74,48.58 64.58,48.58 64.2,48.96 64.2,50.93 63.18,51.94 63.18,56.01 62.8,56.39 55.94,56.39 55.05,57.28 54.23,57.28 53.72,57.78 52.13,57.78
(no net) on TOP: 47.75,58.86 49.66,58.86 49.78,58.99 49.78,60.01 49.72,60.07 47.88,60.07 47.75,59.94
(no net) on BOTTOM: 76.07,63.75 76.07,55.82 77.34,54.55 82.3,54.55 82.3,51.37 82.17,51.24 74.55,51.24 73.41,52.39 73.41,63.63 73.53,63.75
(no net) on BOTTOM: 81.41,61.72 80.71,61.72 80.39,62.04 80.39,63.37 80.01,63.75 77.53,63.75 77.53,58.67 79.88,58.67 80.14,58.93 80.14,60.9 80.58,61.34 81.47,61.34 81.47,61.66
(no net) on BOTTOM: 59.44,54.48 59.44,51.69 58.55,51.69 57.86,52.37 55.68,52.37 55.24,51.94 54.04,51.94 53.91,52.07 53.91,54.1 54.29,54.48
(no net) on BOTTOM: 87.5,54.36 87.5,49.66 87.79,49.37 93.31,49.37 94.36,50.42 94.36,51.94 93.6,52.7 91.38,52.7 90.8,53.28 90.8,54.55 88.71,54.55 88.52,54.36
(no net) on BOTTOM: 60.01,51.43 60.01,54.48 66.8,54.48 67.63,55.31 67.63,62.55 67.82,62.74 70.04,62.74 70.04,51.88 69.6,51.43
(no net) on BOTTOM: 61.79,61.59 62.55,61.59 62.93,61.21 63.94,61.21 64.13,61.4 64.13,66.48 64.39,66.74 65.47,66.74 65.79,66.42 65.79,60.07 62.99,60.07 61.72,61.34 61.72,61.53
(no net) on BOTTOM: 60.39,61.59 59.75,61.59 58.99,60.83 56.64,60.83 56.13,61.34 54.29,61.34 54.04,61.09 54.04,58.29 54.55,57.78 58.8,57.78 58.99,57.98 58.99,59.25 60.45,60.71 60.45,61.53
(no net) on BOTTOM: 97.66,58.8 98.93,57.53 100.96,57.53 100.96,54.67 95.88,54.67 95.88,56.39 95.5,56.77 95.5,58.67 95.63,58.8
(no net) on BOTTOM: 82.99,54.55 82.99,51.37 83.12,51.24 85.85,51.24 85.92,51.31 85.92,54.29 85.66,54.55
AD243X_IOVDD on L4_PWR: 67.06,28.32 101.85,28.32 101.85,33.4 107.7,33.4 107.7,32.77 112.14,32.77 112.14,26.29 70.74,26.29 70.74,23.37 67.06,23.37
AD243X_ISENSEP on BOTTOM: 102.28,53.98 102.89,53.98 102.89,53.24 103.07,53.24 103.07,49.12 102.89,49.12 102.89,48.39 102.28,48.39 102.28,49.12 100.45,49.12 100.45,48.39 99.87,48.39 99.87,49.12 99.57,49.12 99.57,48.89 96.52,48.89 95.88,49.53 95.88,53.47 99.57,53.47 99.57,53.24 99.87,53.24 99.87,53.98 100.45,53.98 100.45,53.24 102.28,53.24
AD243X_VBUS on TOP (solid shape): outline of 548 points within 52.13,48.58 97.92,59.56
AD243X_VBUS on BOTTOM (solid shape): 98.93,57.53 100.96,57.53 100.96,54.67 95.88,54.67 95.88,56.39 95.5,56.77 95.5,58.67 95.63,58.8 97.66,58.8
AD243X_VBUS on BOTTOM (solid shape): 60.45,61.53 60.45,60.71 58.99,59.25 58.99,57.98 58.8,57.78 54.55,57.78 54.04,58.29 54.04,61.09 54.29,61.34 54.67,61.34 54.67,60.54 54.73,60.4 54.88,60.34 55.87,60.34 56.01,60.4 56.07,60.54 56.07,61.16 56.13,61.25 56.24,61.23 56.64,60.83 57.58,60.83 57.75,60.63 58,60.56 58.2,60.6 58.35,60.73 58.43,60.76 58.51,60.73 58.67,60.6 58.86,60.56 59.19,60.7 59.32,61.02 59.32,61.07 59.3,61.15 59.75,61.59 60.39,61.59
AD243X_VBUS on TOP: 2.6,29.34 2.6,26.23 5.84,26.23 5.84,29.34
AD243X_VBUS on L4_PWR: 1.4,69.09 110.62,69.09 110.62,46.42 105.41,46.42 105.41,53.34 95.63,53.34 95.63,59.18 90.68,59.18 90.68,62.48 30.99,62.48 30.99,60.32 5.84,60.32 5.84,10.48 1.4,10.48
AD243X_VOUT1 on BOTTOM: 99.06,40.77 101.22,40.77 101.22,39.12 101.09,38.99 99.19,38.99 99.06,39.12
AD243X_VOUT1 on L4_PWR: 108.08,39.37 105.66,39.37 105.66,36.64 98.81,36.64 98.81,39.88 95.63,39.88 95.63,45.85 102.81,45.85 102.81,43.37 107.54,43.37 107.54,40.21 107.59,40.16 107.95,40.16 108.08,40.03
AD1937_CM on TOP: 57.09,28.96 57.02,29.02 53.02,29.02 52.7,29.34 52.7,31.18 52.64,31.24 52.07,31.24 51.75,30.92 51.75,30.29 51.24,29.78 51.24,28.26 52.45,28.26 52.83,27.88 52.83,27.11 53.02,26.92 56.52,26.92 57.09,27.5
AD1937_CM on L4_PWR: 59.82,28.19 59.82,17.46 49.28,17.46 49.28,10.73 21.84,10.73 21.84,16.51 36.7,16.51 36.7,20.95 47.43,20.95 47.43,26.86 52.96,26.86 52.96,28.38 59.44,28.38 59.44,28.19
LTC4368_SENSE on TOP: 48.97,65.21 46.42,65.21 46.29,65.34 46.29,68.17 46.47,68.35 48.77,68.35 48.97,68.15
LTC4368_SENSE on TOP: 55.63,59.94 55.63,61.28 56.58,62.23 56.58,65.02 56.83,65.28 61.53,65.28 62.55,64.26 62.55,60.13 62.36,59.94
LTC4368_SENSE on BOTTOM: 47.24,68.3 47.24,63.75 58.04,63.75 58.04,68.3
UNNAMED_3_AD243XW_I149_ACM on BOTTOM: 114.2,36.45 115.9,36.45 115.9,34.39 114.53,34.39 113.28,33.15 112.46,33.15 112.27,33.34 112.27,34.85 113.39,34.85 114,35.46 114,36.25
UNNAMED_4_MODRJE7318800XXX_I171_2 on L4_PWR: 174.88,32.38 174.88,14.1 167.77,14.1 167.77,32.38
UNNAMED_5_CAP_I116_N1 on BOTTOM: 133.86,51.82 169.04,51.82 169.42,51.43 169.42,49.53 168.91,49.02 132.72,49.02 131.44,50.29 103.89,50.29 103.89,54.36 102.87,55.37 102.87,57.4 105.92,57.4 106.3,57.02 106.3,53.98 106.68,53.59 108.2,53.59 108.58,53.21 132.46,53.21
UNNAMED_5_CAP_I116_N1 on L4_PWR: 166.94,59.5 166.94,52.32 163.96,52.32 163.96,49.66 166.94,49.66 166.94,38.16 174.88,38.16 174.88,59.5
UNNAMED_8_ADAU145X_I261_AVDD on TOP: 28.65,35 28.65,33.78 28.52,33.66 27.38,33.66 27.38,32.44 32.84,32.44 33.4,31.88 33.4,28.83 34.77,28.83 34.77,32.77 34.04,32.77 33.66,33.15 33.66,34.87 33.53,35 32.72,35 32.72,33.86 32.51,33.66 29.46,33.66 29.34,33.78 29.34,34.92 29.26,35
UNNAMED_8_ADAU145X_I261_DVDD1 on TOP: 22.23,49.91 23.5,49.91 23.62,50.04 23.62,50.42 23.37,50.67 23.37,51.13 22.35,51.13 22.35,50.67 22.1,50.42 22.1,50.04
UNNAMED_8_ADAU145X_I261_DVDD1 on L4_PWR: 37.72,50.93 37.72,46.99 36.7,46.99 36.7,48.01 34.29,48.01 33.91,47.62 33.91,45.34 34.42,44.83 37.72,44.83 37.72,38.1 38.48,37.34 38.99,37.34 38.99,34.8 35.56,34.8 35.56,36.32 35.05,36.83 25.84,36.83 25.84,34.86 20.76,34.86 20.76,40.58 21.21,41.02 23.88,41.02 24.64,41.78 24.64,48.64 24.26,49.02 22.99,49.02 22.1,49.91 22.1,50.93 ; 2 cut-outs
UNNAMED_8_CAP_I189_N2 on TOP: 16.89,58.55 16.89,56.52 19.18,56.52 19.18,58.55
UNNAMED_8_RES_I113_N2 on TOP: 23.5,52.7 22.23,52.7 22.1,52.58 22.1,52.2 22.35,51.94 22.35,51.49 23.37,51.49 23.37,51.94 23.62,52.2 23.62,52.58
UNNAMED_8_RES_I113_N2 on BOTTOM: 26.8,43 33.5,43 33.5,49.71 32.46,49.71 28.45,53.72 22.23,53.72 21.97,53.47 21.97,51.82 22.23,51.56 26.54,51.56 26.8,51.31
UNNAMED_9_AD1937_I165_FILTR on TOP: 43.69,37.53 43.69,34.92 43.94,34.67 45.28,34.67 45.59,34.99 46.74,36.13 48.2,36.13 48.45,36.39 48.45,36.51 48.2,36.77 46.74,36.77 45.97,37.53
UNNAMED_9_AD1937_I165_LF on TOP: 57.91,32.13 57.91,31.62 58.42,31.12 58.55,31.12 58.61,31.05 58.61,30.16 58.55,30.1 57.53,30.1 57.28,30.35 57.28,32.19 57.85,32.19
UNNAMED_9_CAP_I223_N1 on TOP: 57.59,29.53 58.61,29.53 58.8,29.34 58.8,26.23 58.61,26.03 57.59,26.03 57.47,26.16 57.47,29.4
UNNAMED_10_FERRITE_I73_N1 on TOP: 9.08,25.78 9.21,25.65 9.21,24.38 8.83,24 8.83,21.02 8.51,20.7 8.51,18.8 8.38,18.67 8.06,18.67 7.68,19.05 6.86,19.05 6.1,18.29 6.1,17.34 5.08,16.32 3.17,16.32 2.86,16.64 2.86,25.08 3.56,25.78
UNNAMED_11_CAP_I16_N2 on TOP: 123.57,16.76 123.57,14.35 121.92,14.35 121.67,14.61 121.67,16.51 121.92,16.76
UNNAMED_11_CAP_I16_N2 on L4_PWR: 99.38,20.64 99.38,14.1 107.38,14.1 107.38,2.79 114.36,2.79 114.36,14.03 123.7,14.03 123.7,21.53 120.59,21.53 120.59,20.64
UNNAMED_12_ADLT3502_I229_BD on BOTTOM (solid shape): 70.04,51.88 69.6,51.43 62.06,51.43 61.89,51.64 61.64,51.72 61.47,51.68 61.33,51.59 61.26,51.57 61.19,51.59 61.05,51.68 60.88,51.72 60.71,51.68 60.57,51.59 60.5,51.57 60.43,51.59 60.29,51.68 60.12,51.72 60.11,51.72 60.04,51.74 60.01,51.82 60.01,54.48 66.8,54.48 67.63,55.31 67.63,56.31 68.08,56.31 68.23,56.37 68.29,56.52 68.29,57.61 68.23,57.75 68.08,57.81 67.63,57.81 67.63,59.69 67.63,62.55 67.82,62.74 70.04,62.74
UNNAMED_12_ADLT3502_I229_SW on BOTTOM (solid shape): 65.79,66.42 65.79,60.07 62.99,60.07 61.72,61.34 61.72,61.53 61.79,61.59 62.55,61.59 62.8,61.34 62.79,61.31 62.78,61.27 62.78,61.23 62.78,60.65 62.84,60.51 62.98,60.45 63.64,60.45 63.78,60.51 63.84,60.65 63.84,61.11 64.13,61.4 64.13,64.73 65.25,64.73 65.39,64.79 65.45,64.94 65.45,66.13 65.39,66.27 65.25,66.33 64.13,66.33 64.13,66.48 64.39,66.74 65.47,66.74
UNNAMED_12_ADLTC4368V2_I398_GATE on TOP (solid shape): 54.17,66.99 54.17,66.55 54.1,66.48 52.07,66.48 51.94,66.36 51.94,64.71 51.94,64.71 52.07,64.58 54.16,64.58 54.16,63.94 52.01,63.94 51.94,63.88 51.94,62.23 51.94,61.79 52.32,61.4 53.28,61.4 53.4,61.28 53.4,58.81 51.86,58.81 51.81,58.8 51.65,58.8 51.65,59.17 51.6,59.31 51.45,59.37 50.55,59.37 50.55,66.8 50.86,67.12 54.04,67.12
UNNAMED_12_ADP2360_I325_SW on BOTTOM (solid shape): 80.39,63.37 80.39,62.04 80.71,61.72 81.41,61.72 81.47,61.66 81.47,61.34 80.58,61.34 80.56,61.32 80.45,61.32 80.13,61.19 80,60.87 80.03,60.69 80.14,60.54 80.14,58.93 79.88,58.67 77.53,58.67 77.53,63.75 80.01,63.75
UNNAMED_12_CAP_I278_N2 on TOP (solid shape): outline of 235 points within 23.24,54.61 35.94,65.66
UNNAMED_12_CAP_I279_N2 on TOP (solid shape): 41.66,59.82 41.66,57.28 37.72,57.28 37.37,56.93 37.37,55.2 36.78,54.61 35.81,54.61 35.81,59.69 36.32,60.2 41.27,60.2
UNNAMED_12_CAP_I279_N2 on TOP (solid shape): 48.96,61.91 48.9,61.85 48.86,61.85 48.78,61.83 48.71,61.79 46.1,61.79 45.91,61.98 45.91,64.45 46.04,64.58 48.96,64.58
UNNAMED_12_CAP_I279_N2 on TOP (solid shape): 49.78,60.01 49.78,59.38 49.75,59.37 49.64,59.29 49.6,59.17 49.6,58.86 47.75,58.86 47.75,59.94 47.88,60.07 49.72,60.07
UNNAMED_12_CAP_I279_N2 on BOTTOM: 37.66,57.59 49.53,57.59 49.53,63.5 46.86,63.5 46.86,64.58 37.66,64.58
UNNAMED_12_CAP_I301_N2 on BOTTOM (solid shape): 76.07,55.82 77.34,54.55 82.3,54.55 82.3,51.37 82.17,51.24 74.55,51.24 73.41,52.39 73.41,63.63 73.53,63.75 76.07,63.75
UNNAMED_12_DIOLED_I200_P on TOP: 62.61,53.28 62.61,52.32 62.55,52.26 59.56,52.26 59.5,52.32 59.5,53.21 59.63,53.34 62.55,53.34
UNNAMED_12_TRANNMOSFETDUAL_I282_S on TOP: 52.32,65.91 56.13,65.91 56.2,65.85 56.2,62.67 56.13,62.61 52.32,62.61 52.32,63.5 54.55,63.5 54.55,65.09 52.32,65.09
UNNAMED_12_TRANNMOSFETDUAL_I282_S on L3_SIG: 53.21,65.91 53.21,62.99 56.2,62.99 56.2,65.91
UNNAMED_14_CAP_I27_N2 on TOP: 76.64,2.41 76.64,1.27 63.94,1.27 63.75,1.27 63.75,11.56 66.55,11.56 66.55,9.08 77.6,9.08 77.6,2.41
UNNAMED_14_CAP_I27_N2 on BOTTOM: 76.58,1.27 63.94,1.27 63.75,1.27 63.75,9.08 77.72,9.08 77.72,2.16 76.58,2.16
UNNAMED_14_CN4PV4_I1_N2 on TOP: 63.37,9.08 63.37,1.27 51.37,1.27 51.37,2.41 50.36,2.41 50.36,11.56 55.31,11.56 55.31,9.08
UNNAMED_14_CN4PV4_I1_N2 on BOTTOM: 63.37,9.08 63.37,1.27 51.44,1.27 51.44,2.29 50.42,2.29 50.42,9.08
VOUT2_3V3 on TOP: 118.49,34.67 118.11,34.67 117.47,34.04 116.33,35.18 113.92,35.18 113.92,35.69 116.33,35.69 117.47,36.83 118.11,36.2 118.49,36.2 119.38,37.08 122.55,37.08 122.68,36.96 122.68,33.91 122.55,33.78 119.38,33.78
VOUT2_3V3 on BOTTOM: 126.29,38.35 126.29,39.37 121.54,39.37 120.9,38.73 120.9,33.91 121.03,33.78 122.55,33.78 122.68,33.91 122.68,37.97 123.06,38.35
VOUT2_3V3 on L4_PWR: 108.71,39.37 119.38,39.37 119.38,36.45 123.82,36.45 123.82,42.93 110.87,42.93 110.87,40.64 108.97,40.64 108.71,40.39
WKUP_24V on TOP: 42.68,56.83 42.86,56.65 42.86,54.44 42.7,54.28 39.88,54.28 39.69,54.47 39.69,56.68 39.84,56.83
WKUP_24V on L4_PWR: 98.42,39.5 98.42,36.2 106.11,36.2 106.11,38.99 118.94,38.99 118.94,36.07 124.21,36.07 124.21,37.08 141.1,37.08 141.1,29.72 112.52,29.72 112.52,37.59 107.57,37.59 107.57,33.78 73.28,33.78 73.28,54.48 44.83,54.48 44.83,52.39 41.21,52.39 41.21,58.8 77.98,58.8 77.98,39.5

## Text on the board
Ref Des/Silkscreen Bottom: A | C
User.Comments: SEE NOTE 7 | (4 PLACES) | SEE ASSY NOTE #5 | 4.    SEE DETAIL A FOR Y1 INSTALLATION. | 7.    BOARD ASSEMBLY SPECIAL NOTES: (IN ORDER TO MINIMIZE MIC DEVICES (U11-U14) DAMAGE) | 8.    BOARDS TO BE SHIPPED SINGULATED AFTER ASSEMBLY PROCESS. | 5.    U9 IS A DEVICE-SOCKET COMBO AND FOLLOWS THIS SOLDERPASTE INSTRUCTION: | SMOOTHEN EDGES AND FREE FROM BURRS AFTER DEPANELIZATION PROCESS. | A. DO NOT BOARD WASH OR CLEAN AFTER THE REFLOW PROCESS. | C. DO NOT DIRECTLY EXPOSE TO ULTRASONIC PROCESSING, WELDING, OR CLEANING. | E. DO NOT APPLY OVER 30 PSI OF AIR PRESSURE INTO THE PORT HOLE. | B. DO NOT BRUSH BOARD WITH OR WITHOUT SOLVENTS AFTER THE REFLOW PROCESS. | D. DO NOT INSERT ANY OBJECT IN PORT HOLE OF DEVICE AT ANY TIME. | F. DO NOT PULL A VACUUM OVER PORT HOLE OF THE MICROPHONE. | G. DO NOT APPLY A VACUUM WHEN REPACKING INTO SEALED BAGS AT A RATE | SUPPLIED PART | U20(DEVICE) | U20(SOCKET) | FASTER THAN 0.5 ATM/SEC. | INSTALLED SOCKET | INSTALLED PART | INSTALLED DUT | NO PASTEMASK | PASTEMASK | DETAIL A FOR COMPONENT Y1
Ref Des/Assembly Top: MATE ENTRY | A | C
Ref Des/Silkscreen Top: CS3 | 24V | PWM | SELECT | A | GND | CS1 | ADC | IN R | IN L | CLKOUT | C | MCLK | 3V3 | CB | CLOSED | VBUS | ADAU1452 | SOURCE | PDM CLOCK | IRQ | SIO2 | 5V | AD2437 | RESET | VOUT2 | SUB | WAKE-UP | I2C_BUS_SW | MAIN | EVAL-AD2437A1MZ | USBI | GREEN | DISABLE | SELFBOOT_ | LED FUNCTIONS | USBi | YELLOW | USBI SEL | SHIELD A | CS2 | 24V INPUT | INPUT | SENSITIVITY | ADC IN | 1VP-P | 2VP-P | 1 | DAC OUT | CLK_SEL | SPDIF OUT | SPDIF IN | BCLK | PDM_ | CLK | GPIO7 | PG | PORT A | PORT B | TOWARDS SUB | TOWARDS MAIN | BRD | SHIELD
XSECTION_CHART: *  SURFACE | * SOLDERMASK_TOP MASK | L1 TOP CONDUCTOR | *  DIELECTRIC | L2 L2_GND PLANE | L3 L3_SIG CONDUCTOR | L4 L4_PWR CONDUCTOR | L5 L5_GND PLANE | L6 BOTTOM CONDUCTOR | * SOLDERMASK_BOTTOM MASK | DESIGN CROSS SECTION CHART | ___________________________ | TOTAL THICKNESS 62 MIL | 1-6
PAGE_OUTLINE: 15APR22 | 03NOV21 | B | C | D | E | CHANGES AS PER ECR-109621 | CHANGES AS PER ECR-111941 | CHANGES AS PER ECR-113566 | CHANGES AS PER ECR-115079 | 04OCT22 | 27JAN23 | 11APR23 | 08AUG23 | R. WHITNEY | CUSTOMER EVALUATION Z
DIMENSION: " " | (REF) | SEE DETAIL X | DIA MAX | +2/-0 | -
User.11: 1 | A | C | (CHECK DATASHEET)
User.12: A | C
User.15: 32 MILS 370HR | 5 MILS 370HR | 15.    BOARDS TO BE SHIPPED IN ARRAY AND KEEP INTACT. | PANELED SOLDER PASTE STENCIL SHOULD BE SENT TO THE ADI. | PANEL TO BE SUBJECTED TO CUSTOMER'S APPROVAL. | NOTE: ALL IMPEDANCE TOLERANCE +/-10% | LAYER | L3 | L1 | L6 | 100 OHMS DP | 50 OHMS SE | IMPEDANCE | SE = SINGLE ENDED | DP = DIFFERENTIAL PAIR | REFERENCE | L2 | L5 | LINE WIDTH | 9.5MILS | 7 MILS | 6.5MILS | SPACE | N/A | IMPEDANCE TABLE
User.23: L2 GND | 08-      -07
User.24: L3 SIG | 08-      -08
User.25: MATE_ENTRY | C146 | R106 | C141 | C143 | C131 | R97 | R101 | E8 | C138 | C135 | C | C185 | C130 | C178 | C177 | A | C86 | C176 | C85 | R68 | R73 | C89 | R117 | R74 | E4 | C87 | DS2 | C90 | U4 | C81 | R80 | R79 | D8 | R75 | C88 | R83 | R77 | R78 | R76 | C36 | C91 | R81 | C52 | L10 | L3 | L9 | L4 | C38 | C39 | C40 | FL3 | FL2 | C48 | C58 | C41 | C42 | C57 | C61 | C60 | C43 | C44 | P6 | P3 | C94 | C95 | C136 | R114 | C187 | L25 | R143 | C184 | C133 | R142 | R144 | C84 | R115 | C83 | C82 | C182 | R69 | R70 | R82 | C50 | U14 | C35 | C49 | L2 | L8 | L7 | L1 | C54 | C53 | R40 | R41 | R48 | R46 | C93 | C96
User.26: R20 | C13 | C14 | R14 | R15 | C2 | C1 | C3 | R12 | C9 | L10 | L11 | L3 | L4 | P7 | L5 | C34 | C35 | C39 | C36 | C25 | C23 | C24 | C37 | C38 | C26 | D2 | D4 | D3 | P6 | R47 | C52 | C55 | 10 | 32 | 20 | 2 | P2 | R19 | R18 | 25 | 15 | 5 | 1 | C15 | R2 | R13 | R5 | R6 | C6 | R7 | R8 | R4 | R3 | C17 | R9 | R10 | C7 | C8 | R11 | R1 | C12 | C20 | C30 | L9 | L8 | L1 | L2 | C33 | C32 | C19 | C31 | C18 | R26 | R25 | L6 | L7 | L14 | L13 | P10 | P9 | R45 | R46 | R16 | C21 | C22 | C10 | U1 | C11 | C53 | C28 | R23 | R22 | R24 | C51 | R48 | Q1 | E4 | R59 | R58 | R60 | R61 | R62 | R63 | C73 | C69 | C50 | C59 | R55 | LED1 | C70 | C60 | R41 | R43 | C71 | R42 | C61 | E3 | C72 | LED5 | C62 | C54 | R57 | E2 | C56 | C63 | C64 | R51 | C65 | C66 | R52 | R50 | L12 | R53 | LED4 | C67 | R49 | R54 | C57 | C68 | C58 | R56 | R21 | U5 | LED2 | LED3 | JP5 | U4
User.30: L4 PWR | 08-      -09
User.31: L5 GND | 08-      -10
User.45: FIGURE | SIZE | 10.0 | 35.0 | 40.0 | 43.0 | 45.0 | 55.0 | 67.0 | 75.0 | 105.0 | 20.0 | 33.0 | 71.0 | 125.0 | 59.0x31.0 | 79.0x31.0 | PLATED | NON-PLATED | DRILL CHART: TOP to BOTTOM | ALL UNITS ARE IN MILS | QTY | 1141 | 22 | 10 | 8 | 97 | 2 | 3 | 6 | 4 | TOLERANCE/NOTES
